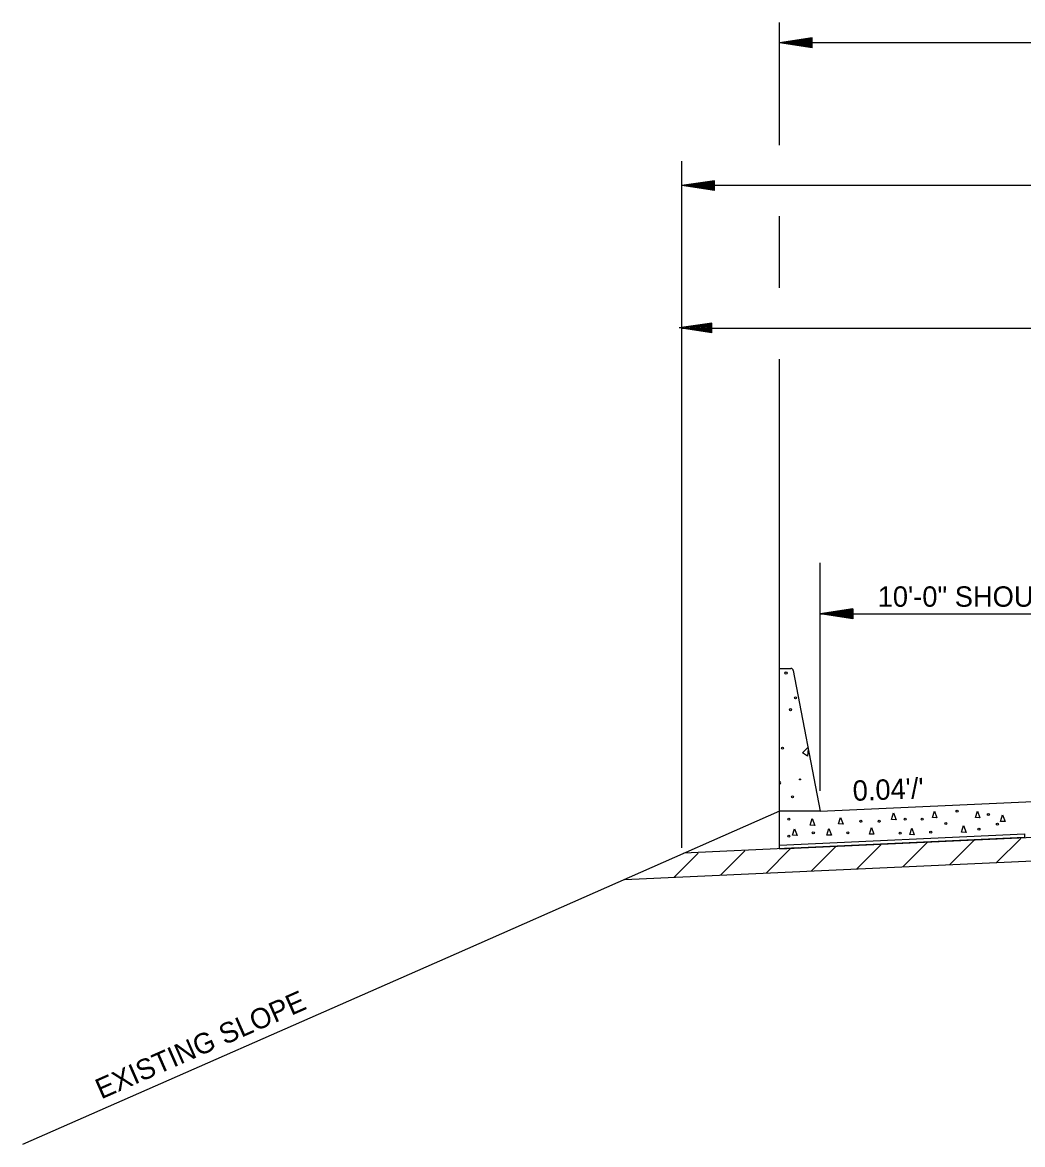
# Model space of a CAD drawing. Extents: x 60325 to 61047, y 53669 to 53767.
# Drawn here: x 60505.99 to 60530.5, y 53685.11 to 53712.62 of the extents above; entities that cross this region are included whole.
import ezdxf

# ---------------------------------------------------------------- set-up
doc = ezdxf.new("R2010")
doc.units = 0
doc.layers.add('R_Border', color=7, linetype='Continuous')
doc.layers.add('R_Border Prem', color=7, linetype='Continuous')

msp = doc.modelspace()

# ---------------------------------------------------------------- linework, layer by layer
at = {"layer": 'R_Border Prem'}
for p, q in [((60524.545, 53709.618), (60524.545, 53712.624)), ((60525.345, 53712.244), (60524.545, 53712.124)), ((60618.545, 53712.124), (60524.545, 53712.124)), ((60525.345, 53712.004), (60524.545, 53712.124)), ((60525.345, 53712.224), (60524.679, 53712.124)), ((60525.345, 53712.024), (60524.679, 53712.124)), ((60525.345, 53712.204), (60524.816, 53712.124)), ((60525.345, 53712.045), (60524.816, 53712.124)), ((60525.345, 53712.184), (60524.95, 53712.124)), ((60525.345, 53712.065), (60524.95, 53712.124)), ((60525.345, 53712.164), (60525.085, 53712.124)), ((60525.345, 53712.086), (60525.085, 53712.124)), ((60525.345, 53712.143), (60525.219, 53712.124)), ((60525.345, 53712.106), (60525.219, 53712.124)), ((60525.345, 53712.004), (60525.345, 53712.244)), ((60522.149, 53696.623), (60522.149, 53709.224)), ((60522.949, 53708.744), (60522.149, 53708.624)), ((60522.949, 53708.504), (60522.949, 53708.744)), ((60619.713, 53708.624), (60522.149, 53708.624)), ((60522.949, 53708.504), (60522.149, 53708.624)), ((60522.949, 53708.724), (60522.283, 53708.624)), ((60522.949, 53708.524), (60522.283, 53708.624)), ((60522.949, 53708.704), (60522.42, 53708.624)), ((60522.949, 53708.545), (60522.42, 53708.624)), ((60522.949, 53708.684), (60522.554, 53708.624)), ((60522.949, 53708.565), (60522.554, 53708.624)), ((60522.949, 53708.664), (60522.689, 53708.624)), ((60522.949, 53708.586), (60522.689, 53708.624)), ((60522.949, 53708.643), (60522.823, 53708.624)), ((60522.949, 53708.606), (60522.823, 53708.624)), ((60524.545, 53706.118), (60524.545, 53707.872)), ((60522.882, 53705.254), (60522.082, 53705.134)), ((60522.882, 53705.234), (60522.216, 53705.134)), ((60522.882, 53705.214), (60522.354, 53705.134)), ((60522.882, 53705.194), (60522.487, 53705.134)), ((60522.882, 53705.174), (60522.622, 53705.134)), ((60522.882, 53705.014), (60522.882, 53705.254)), ((60522.882, 53705.014), (60522.082, 53705.134)), ((60619.713, 53705.124), (60522.149, 53705.124)), ((60522.882, 53705.034), (60522.216, 53705.134)), ((60522.882, 53705.055), (60522.354, 53705.134)), ((60522.882, 53705.075), (60522.487, 53705.134)), ((60522.882, 53705.096), (60522.622, 53705.134)), ((60522.882, 53705.153), (60522.756, 53705.134)), ((60522.882, 53705.116), (60522.756, 53705.134)), ((60524.545, 53693.784), (60524.545, 53704.372)), ((60525.541, 53693.784), (60525.541, 53699.374)), ((60526.341, 53698.244), (60525.541, 53698.124)), ((60525.541, 53698.124), (60534.545, 53698.124)), ((60526.341, 53698.004), (60525.541, 53698.124)), ((60526.341, 53698.224), (60525.675, 53698.124)), ((60526.341, 53698.024), (60525.675, 53698.124)), ((60526.341, 53698.204), (60525.812, 53698.124)), ((60526.341, 53698.045), (60525.812, 53698.124)), ((60526.341, 53698.184), (60525.946, 53698.124)), ((60526.341, 53698.065), (60525.946, 53698.124)), ((60526.341, 53698.163), (60526.081, 53698.124)), ((60526.341, 53698.085), (60526.081, 53698.124)), ((60526.341, 53698.143), (60526.215, 53698.124)), ((60526.341, 53698.106), (60526.215, 53698.124)), ((60526.341, 53698.244), (60526.341, 53698.004)), ((60524.545, 53696.785), (60524.822, 53696.785)), ((60524.545, 53693.284), (60524.545, 53696.785)), ((60524.882, 53696.738), (60525.541, 53693.284)), ((60522.149, 53692.386), (60522.149, 53696.623)), ((60525.541, 53693.284), (60532.545, 53693.604)), ((60524.545, 53693.284), (60516.616, 53689.793)), ((60524.545, 53692.366), (60524.545, 53693.284)), ((60525.541, 53693.284), (60524.545, 53693.284)), ((60524.545, 53692.366), (60532.585, 53692.733)), ((60528.16, 53692.515), (60527.569, 53691.924)), ((60529.31, 53692.568), (60528.718, 53691.976)), ((60530.457, 53692.62), (60529.866, 53692.029)), ((60522.554, 53692.259), (60521.963, 53691.667)), ((60525.015, 53692.387), (60522.203, 53692.259)), ((60523.691, 53692.311), (60523.099, 53691.719)), ((60524.805, 53692.362), (60524.214, 53691.77)), ((60525.918, 53692.413), (60525.327, 53691.821)), ((60527.03, 53692.463), (60526.438, 53691.872)), ((60520.747, 53691.612), (60532.542, 53692.151)), ((60516.616, 53689.793), (60505.989, 53685.113))]:
    msp.add_line(p, q, dxfattribs=at)
for points in [[(60525.25, 53694.813), (60525.232, 53694.636), (60525.107, 53694.714), (60525.242, 53694.85)], [(60525.347, 53693.104), (60525.407, 53692.938), (60525.297, 53692.942), (60525.347, 53693.104)], [(60526.042, 53693.135), (60526.102, 53692.969), (60525.992, 53692.973), (60526.042, 53693.135)], [(60527.34, 53693.243), (60527.4, 53693.077), (60527.29, 53693.082), (60527.34, 53693.243)], [(60528.344, 53693.289), (60528.404, 53693.123), (60528.294, 53693.128), (60528.344, 53693.289)], [(60529.394, 53693.289), (60529.455, 53693.123), (60529.345, 53693.128), (60529.394, 53693.289)], [(60530.012, 53693.197), (60530.073, 53693.031), (60529.963, 53693.035), (60530.012, 53693.197)], [(60524.914, 53692.857), (60524.975, 53692.691), (60524.865, 53692.695), (60524.914, 53692.857)], [(60525.756, 53692.863), (60525.816, 53692.697), (60525.706, 53692.702), (60525.756, 53692.863)], [(60526.799, 53692.888), (60526.859, 53692.722), (60526.749, 53692.726), (60526.799, 53692.888)], [(60527.788, 53692.872), (60527.848, 53692.706), (60527.738, 53692.711), (60527.788, 53692.872)], [(60529.054, 53692.934), (60529.115, 53692.768), (60529.005, 53692.772), (60529.054, 53692.934)]]:
    msp.add_lwpolyline(points, dxfattribs=at)
msp.add_lwpolyline([(60530.547, 53692.734), (60530.547, 53692.64), (60524.545, 53692.366), (60524.545, 53692.452)], close=True, dxfattribs=at)
for centre, radius in [((60524.704, 53696.674), 0.0254), ((60524.934, 53696.065), 0.0254), ((60524.813, 53695.776), 0.0254), ((60524.618, 53694.831), 0.0254), ((60525.047, 53694.066), 0.0127), ((60524.864, 53693.639), 0.0254), ((60524.772, 53693.092), 0.025), ((60526.538, 53693.039), 0.025), ((60526.988, 53693.039), 0.025), ((60527.624, 53693.092), 0.025), ((60528.039, 53693.092), 0.025), ((60528.895, 53693.286), 0.025), ((60529.663, 53693.206), 0.025), ((60525.373, 53692.756), 0.025), ((60526.22, 53692.756), 0.025), ((60528.25, 53692.774), 0.025), ((60528.621, 53692.986), 0.025), ((60529.433, 53692.844), 0.025), ((60529.884, 53692.968), 0.025), ((60524.772, 53692.676), 0.025), ((60527.5, 53692.747), 0.025)]:
    msp.add_circle(centre, radius, dxfattribs=at)
msp.add_arc((60524.548, 53693.981), 0.0254, 264.1751, 95.8413, dxfattribs=at)
msp.add_ellipse((60524.822, 53696.724), major_axis=(0, 0.0619), ratio=0.9997, start_param=4.902487, end_param=6.283185, dxfattribs=at)

# ---------------------------------------------------------------- texts
at = {"layer": 'R_Border'}
msp.add_text('EXISTING SLOPE', height=0.5, rotation=23.765, dxfattribs=at).set_placement((60507.918, 53686.218))
at = {"layer": 'R_Border Prem'}
msp.add_text('10\'-0" SHOULDER', height=0.5, dxfattribs=at).set_placement((60526.95, 53698.299))
msp.add_text("0.04'/'", height=0.5, rotation=2.2906, dxfattribs=at).set_placement((60526.347, 53693.537))

doc.saveas('drawing.dxf')
